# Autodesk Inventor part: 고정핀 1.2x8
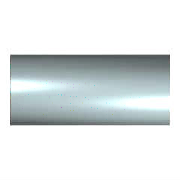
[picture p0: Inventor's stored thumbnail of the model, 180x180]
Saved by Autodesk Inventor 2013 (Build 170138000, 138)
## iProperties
IsCustomPart: 1
Created: 2012-02
Part Number: 고정핀 1.2x8
Material: 강철, 연강
Description: 평행 핀
Document SubType Name: Modeling
Standard: KS B 1320
Designer: P15F
Standards Organization: KS
Language: ko-KR
Size Designation: C 1.2 x  8
Categories: <MemberInstance><Categories><Category DisplayName="조임쇠" InternalName="e4da775c-781d-43d5-af7c-5136215cf5a6" Mnemonic="FSTN"><Category DisplayName="핀" InternalNa
Density: 1 g/cm^3
Author: P15F
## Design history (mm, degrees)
sketch "스케치1"
  geometry: C1 r 0.6 at (0, 0); 1 further point
  constraints: 1 centre point, 1 coincident
  dimensions: "d1" = 1.2 diameter of C1 (= NND)
extrude "본체" new body sketch "스케치1" distance "d2" = 8 (= NLG); taper "d3" = 0 deg
node "작업 평면1"
body "Solid1"
other parameters: "NND" = 1.2 [user parameter; used in 1 equation term], "NLG" = 8 [user parameter; used in 1 equation term], "d8" = 0, "d9" = 0, "d10" = 0
